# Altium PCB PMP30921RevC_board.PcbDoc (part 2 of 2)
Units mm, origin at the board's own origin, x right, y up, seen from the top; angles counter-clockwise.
Board outline 80.01 x 39.37 mm, 2 copper layers (Top Layer, Bottom Layer), stack 1.575 mm thick; 86 components, 35 nets, 198 pads, 30 vias.
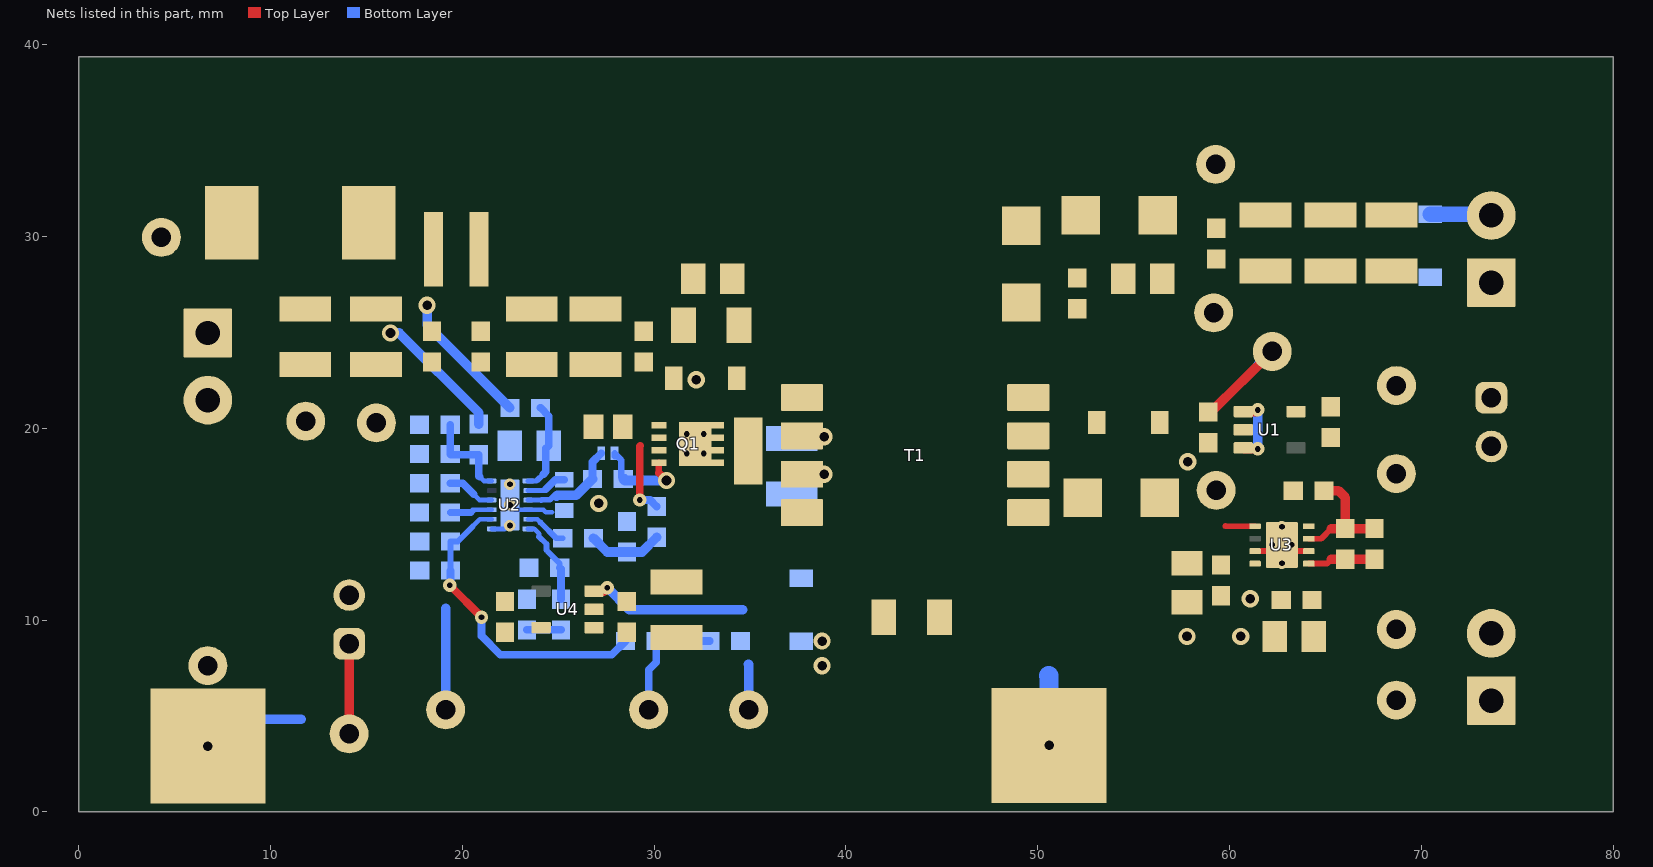
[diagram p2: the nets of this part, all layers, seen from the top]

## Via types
v1: diameter 0.6, hole 0.3, Top Layer to Bottom Layer, 11 vias
v2: diameter 0.9, hole 0.5, Top Layer to Bottom Layer, 8 vias
v3: diameter 0.7, hole 0.3, Top Layer to Bottom Layer, tented top, 3 vias
v4: diameter 0.9, hole 0.5, Top Layer to Bottom Layer, tented top, 2 vias
v5: diameter 0.9, hole 0.5, Top Layer to Bottom Layer, tented both sides, 2 vias
v6: diameter 0.7, hole 0.3, Top Layer to Bottom Layer, tented bottom, 2 vias
v7: diameter 0.7, hole 0.3, Top Layer to Bottom Layer, 1 vias
v8: diameter 0.9, hole 0.5, Top Layer to Bottom Layer, tented bottom, 1 vias

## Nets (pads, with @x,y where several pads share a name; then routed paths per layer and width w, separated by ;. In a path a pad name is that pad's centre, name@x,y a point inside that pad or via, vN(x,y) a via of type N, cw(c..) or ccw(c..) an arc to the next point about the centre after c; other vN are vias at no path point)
FB: C33.2 R15.1 R16.2 U3.3 | length 6.5
  Top Layer w0.31: U3.3@64.135,14.239 64.784,14.239 65.315,14.77
  Top Layer w0.5: R16.2@64.925,16.746 65.675,16.746 66.04,16.381 R15.1@66.04,14.77 ; 65.315,14.77 R15.1@66.04,14.77 ; C33.2@67.564,14.77 R15.1@66.04,14.77
GND: C2.2 C3.2 C4.2 C5.2 C6.2 C7.2 C8.2 C17.2 C22.2 C23.2 C24.2 C25.2 C26.2 C27.2 C28.2 C29.2 C30.2 C31.2 C32.2 Jmp1.2 Jmp5.2 pad.13@6.731,3.429 R8.1 R9.1 R10.1 R14.1 T1.4 TP3.1 TP15.1 TP16.1 TP17.1 U2.4 U2.7 U2.13@22.479,16.002 U4.2 | length 13.8
  Bottom Layer w0.25: U2.7@21.529,14.752 U2.13@22.213,14.752 ; v1(22.479,16.002) 22.729,15.752 U2.4@23.429,15.752 24.23,15.752 24.358,15.625 24.677,15.625
  Bottom Layer w0.5: pad.13@6.731,3.429 8.128,4.826 11.609,4.826 ; TP16.1@19.133,5.32 19.133,10.6
  other v1: 22.479,14.927 22.479,17.077
  other v2: 27.113,16.082
GNDsec: C10.2 C11.2 C12.2 C13.2 C15.2 C16.2 C18.2 C19.2 C20.2 C21.2 C24.1 D3.2 Jmp2.1 Jmp3.2 Jmp4.1 pad.13@50.596,3.463 R16.1 T1.5 TP4.1 TP8.1 TP11.1 U1.2 U3.2 U3.4 U3.7 U3.9 | length 6.7
  Top Layer w0.31: U3.7@61.335,13.589 62.41,13.589 U3.9@62.735,13.914 63.06,13.589 U3.2@64.135,13.589
  Bottom Layer w1: 50.577,7.098 50.596,7.079 pad.13@50.596,3.463
  other v1: 62.735,12.964 62.23,13.919 63.246,13.919 62.735,14.864
  other v2: 57.785,9.144 60.583,9.144 61.086,11.111 57.825,18.247
NetC1_1: C1.1 R1.1
NetC1_2: C1.2 D1.2 T1.8
NetC2_1: C2.1 C3.1 C4.1 D9.1 L1.1 R3.2 R4.2 | length 14.1
  Bottom Layer w0.5: v4(16.256,24.968) 16.705,24.968 20.857,20.816 R3.2@20.857,20.217 ; v2(18.161,26.416) 18.161,25.38 R4.2@22.479,21.062
NetC5_1: C5.1 C6.1 C7.1 C8.1 C9.1 L1.2 R2.2 T1.1
NetC9_2: C9.2 D4.1 R2.1
NetC10_1: C10.1 C11.1 C12.1 C13.1 D2.1 D3.1 Jmp2.2 R1.2 TP2.1 | length 3.2
  Bottom Layer w0.8: D3.1@70.475,31.16 73.588,31.16 Jmp2.2@73.65,31.097
NetC14_1: C14.1 D4.2 pad.14 Q1.5 Q1.6 Q1.7 Q1.8 Q1.9 T1.2
  other v1: 31.702,18.689 32.591,18.689 31.702,19.705 32.591,19.705
  other v4: 32.19,22.526
  other v5: 38.862,19.558
NetC14_2: C14.2 D6.2 T1.3
  other v5: 38.862,17.603
NetC15_1: C15.1 D5.1 TP5.1 U1.1 U1.3 | length 8.7
  Top Layer w0.5: C15.1@58.896,20.846 59.034,20.846 TP5.1@62.23,24.003 ; U1.3@60.718,18.971 60.766,18.923 v3(61.468,18.923) ; U1.1@60.718,20.871 61.384,20.871 v3(61.468,20.955)
  Bottom Layer w0.5: v3(61.468,18.923) v3(61.468,20.955) ; 61.468,23.28 TP5.1@61.843,23.656
NetC16_1: C16.1 Jmp3.1 TP6.1 U1.5
NetC17_1: C17.1 R4.1 U2.1 | length 4.7
  Bottom Layer w0.25: U2.1@23.429,17.252 23.878,17.252 23.909,17.283
  Bottom Layer w0.3: 23.909,17.283 24.23,17.605 24.23,17.607
  Bottom Layer w0.4: R4.1@24.079,21.062 24.511,20.63 C17.1@24.511,19.094 24.358,18.94 24.358,17.734 24.23,17.607
NetC18_1: C18.1 C19.1 D8.1 TP9.1 U3.5 U3.8 | length 1.6
  Top Layer w0.31: 59.784,14.897 59.792,14.889 U3.5@61.335,14.889
NetC20_1: C20.1 C21.1 C33.1 Jmp4.2 R15.2 TP10.1 U3.1 | length 3.5
  Top Layer w0.31: U3.1@64.135,12.939 65.084,12.939 65.315,13.17
  Top Layer w0.5: 65.315,13.17 R15.2@66.04,13.17 C33.1@67.564,13.17
NetC22_1: C22.1 U2.2 | length 2.1
  Bottom Layer w0.25: U2.2@23.429,16.752 24.279,16.752 24.346,16.819
  Bottom Layer w0.4: 24.346,16.819 24.84,17.314 C22.1@25.312,17.314
NetC23_1: C23.1 R6.2 R7.1 | length 3.9
  Bottom Layer w0.5: R6.2@26.835,14.268 27.557,13.545 C23.1@28.584,13.545 29.367,13.545 R7.1@30.138,14.316
NetC25_1: C25.1 R3.1 R9.2 U2.12 | length 4.9
  Bottom Layer w0.25: 20.903,17.466 21.117,17.252 U2.12@21.529,17.252
  Bottom Layer w0.4: C25.1@19.371,20.179 R9.2@19.371,18.655 19.409,18.617 R3.1@20.857,18.617 20.857,17.512 20.903,17.466
NetC26_1: C26.1 R11.2 U2.6 | length 4.6
  Bottom Layer w0.25: U2.6@23.429,14.752 23.742,14.752 24.003,14.491 24.003,14.346
  Bottom Layer w0.3: 24.003,14.346 24.385,13.964 24.385,13.648 24.485,13.548 24.485,13.543 25.079,12.949 C26.1@25.079,12.731
  Bottom Layer w0.4: C26.1@25.079,12.731 25.146,12.663 R11.2@25.146,11.087
NetC27_1: C27.1 Jmp5.1 TP12.1 U4.5 | length 4.7
  Top Layer w0.5: TP12.1@14.097,4.064 Jmp5.1@14.097,8.763
NetC28_1: C28.1 U2.9 | length 2.2
  Bottom Layer w0.25: 20.544,15.697 20.599,15.752 U2.9@21.529,15.752
  Bottom Layer w0.35: C28.1@19.371,15.607 20.453,15.607 20.544,15.697
NetC29_1: C29.1 R11.1 | length 1.8
  Bottom Layer w0.4: C29.1@23.368,9.487 R11.1@25.146,9.487
NetC30_1: C30.1 R12.2 R14.2 U2.8 | length 16.5
  Top Layer w0.4: v6(19.343,11.815) 20.998,10.159 v6(20.998,10.146)
  Bottom Layer w0.25: 20.544,14.882 20.914,15.252 U2.8@21.529,15.252
  Bottom Layer w0.3: C30.1@19.381,12.577 R14.2@19.381,14.101 19.763,14.101 20.544,14.882
  Bottom Layer w0.4: v6(19.343,11.815) 19.381,11.853 C30.1@19.381,12.577 ; v6(20.998,10.146) 20.998,9.171 21.977,8.192 27.793,8.192 R12.2@28.509,8.908
NetC31_1: C31.1 C32.1 D6.1 R13.2 TP14.1 U4.1 U4.3 | length 10.7
  Top Layer w0.5: U4.3@26.863,11.509 27.384,11.509 v3(27.559,11.684)
  Bottom Layer w0.5: v3(27.559,11.684) 28.701,10.542 34.622,10.542 ; 34.916,7.704 34.931,7.69 TP14.1@34.931,5.316
  other v2: 38.757,7.622
  other v8: 38.757,8.904
NetD1_1: D1.1 D2.2
NetD5_2: D5.2 T1.7
NetD7_1: D7.1 R5.1 U2.3 | length 5.3
  Bottom Layer w0.25: U2.3@23.429,16.252 24.119,16.252
  Bottom Layer w0.3: 24.119,16.252 24.137,16.27 24.574,16.27 24.768,16.464 24.909,16.464
  Bottom Layer w0.4: R5.1@26.788,17.352 26.788,18.239 D7.1@27.238,18.689
  Bottom Layer w0.5: 24.909,16.464 24.959,16.514 25.95,16.514 R5.1@26.788,17.352
NetD7_2: D7.2 Q1.4 R5.2 | length 5.2
  Top Layer w0.34: 30.251,17.67 Q1.4@30.251,18.205
  Top Layer w0.4: 30.251,17.67 v2(30.646,17.276)
  Bottom Layer w0.34: D7.2@27.938,18.539 D7.2@27.938,18.689 28.288,18.339 28.288,17.451 R5.2@28.388,17.352 R5.2@28.487,17.45
  Bottom Layer w0.5: R5.2@28.388,17.352 28.464,17.276 v2(30.646,17.276)
NetD8_2: D8.2 T1.6
NetD9_2: D9.2 Jmp1.1 TP1.1
NetQ1_1: Q1.1 Q1.2 Q1.3 R7.2 R8.2 | length 3.9
  Top Layer w0.4: v7(29.249,16.26) 29.249,19.053 29.277,19.081
  Bottom Layer w0.4: v7(29.249,16.26) 29.795,16.26 R7.2@30.138,15.916
NetR6_1: R6.1 U2.5 | length 2.2
  Bottom Layer w0.25: U2.5@23.429,15.252 23.913,15.252 24.079,15.086
  Bottom Layer w0.3: 24.079,15.086 24.898,14.268 R6.1@25.235,14.268
NetR10_2: R10.2 U2.10 | length 2.5
  Bottom Layer w0.25: 20.599,16.556 20.903,16.252 U2.10@21.529,16.252
  Bottom Layer w0.4: R10.2@19.371,17.131 20.024,17.131 20.599,16.556
NetR12_1: R12.1 R13.1 TP13.1 | length 6.5
  Bottom Layer w0.4: TP13.1@29.718,5.32 29.718,7.405 30.109,7.796 R12.1@30.109,8.908 32.901,8.908 R13.1@32.901,8.905
pads on no net: U1.4 U2.11 U2.13@22.479,15.317 U2.13@22.479,16.687 U3.6 U4.4

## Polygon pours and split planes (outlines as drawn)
NetC14_2 on Top Layer "TOP_LAYER_NETC14_2_P015" (solid, remove dead copper, pour order 15): 36.598,18.411 38.872,18.415 cw(c38.872,17.917) 39.37,17.917 39.37,17.274 cw(c38.969,17.274) 38.969,16.873 36.752,16.873 cw(c36.752,17.248) 36.377,17.248 36.377,18.189 cw(c36.598,18.189)
GND on Top Layer "TOP_LAYER_GND_P056" (solid, remove dead copper, pour order 56): 3.744,23.218 9.702,23.218 10.461,23.978 29.963,23.978 30.189,23.752 30.189,21.468 29.955,21.234 27.627,21.234 27.362,20.97 27.362,19.265 28.276,18.351 29.249,18.351 29.859,17.741 29.859,16.87 30.346,16.382 41.309,16.382 42.621,15.07 42.621,11.684 41.225,10.287 27.393,10.287 27.301,10.195 3.744,10.195
NetC27_1 on Top Layer "TOP_LAYER_NETC27_1_P055" (solid, remove dead copper, pour order 55): 24.688,9.908 12.913,9.908 12.827,9.821 12.827,7.319 13.161,6.985 22.485,6.985 24.688,9.188
NetC31_1 on Top Layer "TOP_LAYER_NETC31_1_P053" (solid, remove dead copper, pour order 53): 39.397,9.982 26.319,9.982 26.319,8.011 27.218,7.112 39.367,7.112
NetC14_1 on Top Layer "TOP_LAYER_NETC14_1_P052" (solid, remove dead copper, pour order 52): 32.27,16.946 cw(c32.27,17.955) 31.261,17.955 31.282,20.523 ccw(c30.312,20.523) 30.998,21.209 30.678,21.529 cw(c31.208,22.06) 30.458,22.06 30.458,23.068 cw(c30.849,23.068) 30.849,23.458 31.694,23.458 cw(c31.694,22.17) 32.982,22.17 ccw(c33.961,22.17) 33.961,21.192 34.909,21.192 cw(c34.909,19.893) 35.828,20.811 ccw(c36.903,21.887) 36.903,20.366 38.759,20.366 cw(c38.759,19.646) 39.479,19.646 39.479,19.627 cw(c38.606,19.627) 38.606,18.754 36.318,18.754 ccw(c36.318,18.351) 35.915,18.351 35.915,17.261 cw(c35.599,17.261) 35.599,16.946
NetQ1_1 on Top Layer "TOP_LAYER_NETQ1_1_P047" (solid, remove dead copper, pour order 47): 30.646,18.673 28.487,18.673 27.852,19.308 27.852,20.742 27.99,20.88 30.646,20.88
GNDsec on Top Layer "TOP_LAYER_GNDSEC_P045" (solid, remove dead copper, pour order 45): 44.196,13.335 45.085,14.224 48.472,14.224 51.833,10.863 51.833,9.242 44.196,9.242
GND on Top Layer "TOP_LAYER_GND_P044" (solid, remove dead copper, pour order 44): 42.596,9.193 41.343,9.193 39.37,11.166 39.026,11.166 37.875,12.317 37.875,14.193 42.018,14.193 42.621,13.589
NetC16_1 on Top Layer "TOP_LAYER_NETC16_1_P037" (solid, remove dead copper, pour order 37): 75.438,23.4 74.305,24.533 65.319,24.533 62.927,22.141 62.927,20.636 62.865,20.574 70.489,20.574 75.438,20.574
NetC15_1 on Top Layer "TOP_LAYER_NETC15_1_P036" (solid, remove dead copper, pour order 36): 55.88,19.706 57.121,19.706 57.697,20.282 59.382,20.282 59.621,20.521 61.155,20.521 61.292,20.659 61.292,21.195 61.086,21.401 58.412,21.401 58.07,21.059 55.88,21.059
GNDsec on Top Layer "TOP_LAYER_GNDSEC_P035" (solid, remove dead copper, pour order 35): 54.465,19.501 57.856,19.501 58.171,19.816 59.545,19.816 59.993,20.265 64.316,20.265 69.809,20.265 75.404,20.265 75.404,16.254 68.327,16.254 66.448,18.133 54.356,18.133
GNDsec on Top Layer "TOP_LAYER_GNDSEC_P034" (solid, remove dead copper, pour order 34): 54.907,10.194 58.517,10.194 58.838,10.515 58.811,10.542 58.811,11.811 55.516,11.811 55.118,12.209 55.118,18.344 55.516,18.742 55.516,23.58 54.744,23.58 53.751,22.587 53.751,11.342
NetC18_1 on Top Layer "TOP_LAYER_NETC18_1_P032" (solid, remove dead copper, pour order 32): 55.372,17.471 55.372,13.492 56.581,12.283 61.206,12.283 61.593,12.67 61.593,13.07 61.493,13.17 60.968,13.17 60.642,13.495 60.277,13.859 60.277,17.471
GNDsec on Top Layer "TOP_LAYER_GNDSEC_P031" (solid, remove dead copper, pour order 31): 63.859,15.662 64.473,15.047 64.473,14.692 63.819,14.692 63.575,14.448 63.575,12.499 63.291,12.215 63.291,7.552 63.73,7.112 75.404,7.112 75.438,7.146 75.438,4.318 56.359,4.318 47.738,12.939 47.738,15.957 48.097,16.316 50.78,16.291 50.78,15.096 51.431,14.445 53.59,14.445 56.224,11.811 61.397,11.811 61.95,12.364 61.95,16.596 62.575,17.221 63.859,17.221
NetC20_1 on Top Layer "TOP_LAYER_NETC20_1_P030" (solid, remove dead copper, pour order 30): 75.438,7.874 64.014,7.874 63.73,8.158 63.73,13.115 64.434,13.115 65.315,12.233 65.315,11.042 65.689,10.668 75.438,10.668
GNDsec on Top Layer "TOP_LAYER_GNDSEC_P029" (solid, remove dead copper, pour order 29): 75.438,25.33 61.809,25.33 57.949,21.47 52.65,21.47 52.65,23.582 53.602,24.533 53.602,25.654 53.965,26.017 57.794,26.017 58.584,26.807 58.584,29.259 75.008,29.259 75.438,28.829
NetD8_2 on Top Layer "TOP_LAYER_NETD8_2_P028" (solid, remove dead copper, pour order 28): 52.916,18.301 cw(c52.916,17.869) 53.348,17.869 53.348,15.38 cw(c53.051,15.38) 53.051,15.083 51.572,15.083 cw(c51.572,15.603) 51.052,15.603 51.052,16.284 ccw(c50.462,16.284) 50.462,16.873 48.222,16.873 cw(c48.222,17.35) 47.745,17.35 47.745,17.822 cw(c48.224,17.822) 48.224,18.301
NetD5_2 on Top Layer "TOP_LAYER_NETD5_2_P027" (solid, remove dead copper, pour order 27): 52.753,18.896 ccw(c52.753,19.706) 53.563,19.706 53.563,20.823 ccw(c53.348,20.823) 53.348,21.038 52.753,21.038 ccw(c52.753,19.937) 51.975,20.715 cw(c51.052,21.638) 51.052,20.333 48.19,20.333 ccw(c48.19,19.882) 47.738,19.882 47.738,19.255 ccw(c48.097,19.255) 48.097,18.896
NetC10_1 on Top Layer "TOP_LAYER_NETC10_1_P025" (solid, remove dead copper, pour order 25): 55.807,26.779 55.807,29.188 55.118,29.877 55.118,32.319 57.47,34.671 74.531,34.671 75.438,33.764 75.438,30.258 75.057,29.877 60.547,29.877 60.536,29.888 57.904,29.888 57.904,26.779
NetC1_1 on Top Layer "TOP_LAYER_NETC1_1_P024" (solid, remove dead copper, pour order 24): 51.335,27.308 52.678,27.308 53.09,26.897 55.118,26.897 55.118,28.69 51.442,28.69 51.335,28.583
NetD1_1 on Top Layer "TOP_LAYER_NETD1_1_P023" (solid, remove dead copper, pour order 23): 52.466,29.072 ccw(c52.466,30.208) 53.602,30.208 53.602,31.842 ccw(c52.597,31.842) 52.597,32.847 48.659,32.847 ccw(c48.659,32.008) 47.82,32.008 47.82,29.711 ccw(c48.459,29.711) 48.459,29.072
NetC1_2 on Top Layer "TOP_LAYER_NETC1_2_P022" (solid, remove dead copper, pour order 22): 51.201,20.871 48.402,20.871 cw(c48.402,21.619) 47.653,21.619 47.653,27.251 cw(c48.459,27.251) 48.459,28.057 49.876,28.057 cw(c49.876,27.308) 50.625,27.308 ccw(c51.154,27.308) 51.154,26.779 52.474,26.779 cw(c52.474,26.468) 52.785,26.468 52.785,25.33 cw(c50.31,25.33) 52.06,23.58 ccw(c52.98,22.66) 51.679,22.66 51.679,21.349 cw(c51.201,21.349)
NetC9_2 on Top Layer "TOP_LAYER_NETC9_2_P007" (solid, remove dead copper, pour order 7): 33.655,28.956 34.725,28.956 cw(c34.725,28.43) 35.251,28.43 35.251,22.26 cw(c34.774,22.26) 34.774,21.783 33.818,21.783 cw(c33.818,22.225) 33.376,22.225 33.376,28.677 cw(c33.655,28.677)
NetC5_1 on Top Layer "TOP_LAYER_NETC5_1_P006" (solid, remove dead copper, pour order 6): 20.345,24.482 20.345,33.02 35.687,33.02 38.608,30.099 38.608,20.834 36.489,20.834 36.264,21.059 36.264,28.482 35.413,29.333 33.192,29.333 32.67,28.811 32.67,24.982 32.17,24.482
NetC2_1 on Top Layer "TOP_LAYER_NETC2_1_P003" (solid, remove dead copper, pour order 3): 10.461,24.482 18.999,24.482 18.999,33.02 10.461,33.02
NetD9_2 on Top Layer "TOP_LAYER_NETD9_2_P002" (solid, remove dead copper, pour order 2): 9.398,23.6 9.398,33.02 3.81,33.02 3.81,23.638
GND on Bottom Layer "BOTTOM_LAYER_GND_P064" (solid, remove dead copper, pour order 64): 22.729,14.452 22.886,14.452 24.003,13.335 24.003,10.696 23.843,10.536 22.707,10.536 21.971,11.271 21.971,14.452
NetC14_1 on Bottom Layer "BOTTOM_LAYER_NETC14_1_P063" (solid, remove dead copper, pour order 63): 32.282,16.914 cw(c32.282,17.923) 31.273,17.923 31.295,20.491 ccw(c30.324,20.491) 31.011,21.178 30.69,21.498 cw(c31.221,22.028) 30.471,22.028 30.471,23.036 cw(c30.861,23.036) 30.861,23.427 31.707,23.427 cw(c31.707,22.139) 32.995,22.139 ccw(c33.973,22.139) 33.973,21.16 34.921,21.16 cw(c34.921,19.861) 35.84,20.78 ccw(c36.916,21.855) 36.916,20.334 38.772,20.334 cw(c38.772,19.614) 39.492,19.614 39.492,19.595 cw(c38.619,19.595) 38.619,18.722 36.331,18.722 ccw(c36.331,18.319) 35.928,18.319 35.928,17.23 cw(c35.612,17.23) 35.612,16.914
GND on Bottom Layer "BOTTOM_LAYER_GND_P062" (solid, remove dead copper, pour order 62): 3.731,2.455 14.175,2.455 14.941,3.221 14.941,20.877 15.994,21.93 21.61,21.93 22.404,21.137 22.404,19.534 22.845,19.094 23.776,20.025 26.868,20.025 28.151,21.308 29.6,21.308 29.6,23.389 30.189,23.978 32.19,23.978 32.695,24.482 32.695,28.835 33.192,29.333 35.413,29.333 36.264,28.482 36.264,21.059 36.489,20.834 38.608,20.834 38.608,30.099 35.687,33.02 3.81,33.02
GND on Bottom Layer "BOTTOM_LAYER_GND_P060" (solid, remove dead copper, pour order 60): 21.835,20.11 21.835,17.702 21.985,17.552 21.985,11.257 22.987,11.257 22.987,17.942 23.122,18.078 23.122,20.11
GND on Bottom Layer "BOTTOM_LAYER_GND_P058" (solid, remove dead copper, pour order 58): 21.717,14.859 21.083,14.859 20.382,14.158 20.382,11.951 19.999,11.569 18.5,11.569 18.5,20.755 18.351,20.904 17.244,20.904 16.891,20.551 16.891,19.685 15.706,18.5 15.706,10.904 17.062,9.548 20.868,9.548 21.75,10.43
GND on Bottom Layer "BOTTOM_LAYER_GND_P040" (solid, remove dead copper, pour order 40): 29.309,14.346 28.067,14.346 27.585,14.992 24.475,14.992 23.829,15.639 23.829,15.755 24.079,16.006 26.208,16.006 26.829,16.627 29.309,16.627
GNDsec on Bottom Layer "BOTTOM_LAYER_GNDSEC_P039" (solid, remove dead copper, pour order 39): 56.962,20.244 56.962,20.483 61.809,25.33 74.892,25.33 75.404,25.842 75.404,33.798 74.531,34.671 48.471,34.671 47.564,33.764 47.564,20.32
GNDsec on Bottom Layer "BOTTOM_LAYER_GNDSEC_P038" (solid, remove dead copper, pour order 38): 47.564,17.1 47.564,20.678 47.925,21.038 58.057,21.038 61.552,24.533 74.305,24.533 75.404,23.434 75.404,16.306 68.274,16.306 67.441,16.306 65.841,17.907 58.801,17.907 58.007,17.113
GNDsec on Bottom Layer "BOTTOM_LAYER_GNDSEC_P033" (solid, remove dead copper, pour order 33): 75.438,4.318 47.564,4.318 47.564,17.84 47.885,18.161 60.028,18.161 60.968,17.221 65.565,17.221 67.266,15.52 68.289,15.52 69.078,14.731 69.078,13.038 75.047,13.038 75.438,12.647
NetC31_1 on Bottom Layer "BOTTOM_LAYER_NETC31_1_P017" (solid, remove dead copper, pour order 17): 39.338,11.148 34.516,11.148 33.909,10.541 33.909,8.17 34.967,7.112 39.338,7.112
NetC14_2 on Bottom Layer "BOTTOM_LAYER_NETC14_2_P016" (solid, remove dead copper, pour order 16): 36.221,18.387 38.806,18.387 cw(c38.806,17.823) 39.37,17.823 39.37,12.465 cw(c38.528,12.465) 38.528,11.623 36.76,11.623 cw(c36.76,12.555) 35.828,12.555 35.828,18.017 cw(c36.221,18.017) 36.221,18.411

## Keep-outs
Keep-Out Layer:
  text ".Layer_Name" at 14.656,-21.806 h1.52

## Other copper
Top Layer:
  text ".Layer_Name" at 14.656,-21.806 h1.52
Bottom Layer:
  text ".Layer_Name" at 14.656,-21.806 h1.52

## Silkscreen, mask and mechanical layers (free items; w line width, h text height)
Top Overlay:
  text "'.PRJ_Number'.PCB_Rev" at 25.82,35.179 h2
  text "12Vs" at 79.055,29.472 h1 r90
  text "GND2" at 79.113,24.964 h1 r90
  text "VIN" at 1.897,24.119 h1 r90
  text "5Vs" at 77.15,20.672 h1 r90
  text "GND" at 1.897,19.284 h1 r90
  text "GND2" at 77.15,15.947 h1 r90
  text "GND" at 9.497,10.987 h1
  text "GND" at 5.414,9.48 h1
  text "5Vp" at 9.497,8.549 h1
  text "3.3Vs" at 79.113,8.182 h1 r90
  text "GND2" at 79.113,2.739 h1 r90
  text "priFB" at 33.76,2.588 h1
  text "AGND" at 18.241,2.455 h1
  text "NWA" at 29.401,2.421 h1
  text "LM51551 Flyback/SEPIC" at 54.571,0.749 h0.8
  text "10/2020" at 74.051,0.616 h0.8
  text ".Layer_Name" at 14.656,-21.806 h1.52
Bottom Overlay:
  text ".Layer_Name" at 14.656,-21.806 h1.52
Top Paste:
  text ".Layer_Name" at 14.656,-21.806 h1.52
Bottom Paste:
  text ".Layer_Name" at 14.656,-21.806 h1.52
Top Solder:
  text ".Layer_Name" at 14.656,-21.806 h1.52
  text ".Layer_Name" at 14.656,-21.806 h1.52
Bottom Solder:
  text "'.PRJ_Number' '.PCB_Rev'" at 22.871,30.129 h1.5
  text ".Layer_Name" at 14.656,-21.806 h1.52
Drill Guide:
  text ".Layer_Name" at 14.656,-21.806 h1.52
M1 Board Outline:
  the board outline again, w0.254
  text ".Layer_Name" at 14.656,-21.806 h1.52
M2 Board Dimensions:
  rectangle: 0,-6.985 3.175,-3.81
  rectangle: 3.175,-10.16 12.7,-6.985
  lines w0.178: 0,-6.985 25.4,-6.985 ; 3.175,-10.16 3.175,-3.81 ; 6.35,-10.16 6.35,-3.81 ; 12.7,-10.16 12.7,-3.81 ; 19.05,-10.16 19.05,-3.81 ; 0,-10.16 25.4,-10.16 25.4,-3.81 0,-3.81 0,-10.16
  text "'.Print_Date'  '.Print_Time'" at 4.098,40.144 h1.5
  text ".Layer_Name" at 14.656,-21.806 h1.52
M3 3D STEP Top:
  text ".Layer_Name" at 14.656,-21.806 h1.52
M4 3D STEP Bottom:
  text ".Layer_Name" at 14.656,-21.806 h1.52
M5 Assembly Top:
  lines w0.254: -7.417,-23.626 160.223,-23.626 ; -7.417,-18.462 160.274,-18.462 ; -7.417,-13.297 -7.417,-28.791 94.31,-28.791 160.274,-28.791 160.274,-13.297 -7.404,-13.297 -7.404,-28.791 32.614,-28.791 ; 55.194,-28.791 55.194,-13.297 ; 87.376,-18.462 87.376,-13.297 ; 108.712,-18.462 108.712,-13.297 ; 124.511,-28.956 124.511,-23.804
  text "COMPONENTS MARKED 'DNP' SHOULD NOT BE POPULATED." at 29.299,-8.09 h1.52
  text "ASSEMBLY VARIANT:" at 29.286,-11.024 h1.52
  text ".VariantName" at 55.601,-11.024 h1.52
  text "PCB VIEWED FROM TOP SIDE" at -5.804,-16.654 h1.52
  text "BOARD #:" at 57.099,-16.654 h1.52
  text ".PRJ_Number" at 70.955,-16.654 h1.52
  text "REV:" at 92.405,-16.654 h1.52
  text ".PCB_Rev" at 99.809,-16.654 h1.52
  text "SVN REV:" at 113.69,-16.654 h1.52
  text ".VersionControl_RevNumber" at 126.543,-16.654 h1.52
  text "TID #:" at 57.099,-21.819 h1.52
  text ".TID" at 70.955,-21.819 h1.52
  text "PLOT NAME =" at -5.804,-27.034 h1.52
  text ".plot_File_Name" at 14.656,-27.034 h1.52
  text "GENERATED    :" at 57.15,-27.034 h1.52
  text ".Print_Date" at 79.235,-27.034 h1.52
  text ".Print_Time" at 97.752,-27.034 h1.52
  text "TEXAS INSTRUMENTS" at 129.87,-27.034 h1.52
M6 Assembly Bottom:
  lines w0.254: -7.429,-18.474 160.261,-18.474 ; -7.379,-23.639 160.261,-23.639 ; 28.334,-28.969 28.334,-23.817 ; 44.133,-18.474 44.133,-13.31 ; 65.468,-18.474 65.468,-13.31 ; 97.65,-28.804 97.65,-13.31 ; 120.231,-28.804 160.249,-28.804 160.249,-13.31 -7.429,-13.31 -7.429,-28.804 58.534,-28.804 160.261,-28.804 160.261,-13.31
  text "COMPONENTS MARKED 'DNP' SHOULD NOT BE POPULATED." at 154.991,-8.077 h1.52
  text ".VariantName" at 128.473,-11.024 h1.52
  text "ASSEMBLY VARIANT:" at 154.864,-11.024 h1.52
  text ".VersionControl_RevNumber" at 26.302,-16.667 h1.52
  text "SVN REV:" at 39.154,-16.667 h1.52
  text ".PCB_Rev" at 53.035,-16.667 h1.52
  text "REV:" at 60.439,-16.667 h1.52
  text ".PRJ_Number" at 81.89,-16.667 h1.52
  text "BOARD #:" at 95.745,-16.667 h1.52
  text "PCB VIEWED FROM BOTTOM SIDE" at 158.648,-16.667 h1.52
  text ".TID" at 81.89,-21.831 h1.52
  text "TID #:" at 95.745,-21.831 h1.52
  text "TEXAS INSTRUMENTS" at 22.974,-27.047 h1.52
  text ".Print_Time" at 55.093,-27.047 h1.52
  text ".Print_Date" at 73.609,-27.047 h1.52
  text "GENERATED    :" at 95.694,-27.047 h1.52
  text ".plot_File_Name" at 138.189,-27.047 h1.52
  text "PLOT NAME =" at 158.648,-27.047 h1.52
M9 Title Sheet:
  drawing of 57 lines, arcs and shapes, not listed
  text "1" at 18.792,204.127 h1.78
  text "2" at 82.182,204.127 h1.78
  text "3" at 145.411,204.127 h1.78
  text "4" at 209.08,204.127 h1.78
  text "5" at 272.555,204.127 h1.78
  text "6" at 336.182,204.127 h1.78
  text "A" at -10.579,175.095 h1.78
  text "A" at 365.341,175.095 h1.78
  text "B" at -10.579,114.643 h1.78
  text "B" at 365.341,114.643 h1.78
  text "C" at -10.579,54.318 h1.78
  text "C" at 365.341,54.318 h1.78
  text "PROJECT TITLE:" at 288.125,7.048 h1.14
  text ".PRJ_Title" at 289.395,3.662 h1.78
  text "DESIGNED FOR:" at 288.125,-0.597 h1.14
  text ".PRJ_Customer" at 289.395,-4.153 h1.78
  text "D" at -10.579,-5.88 h1.78
  text "D" at 365.341,-5.88 h1.78
  text "FILE NAME:" at 288.125,-8.217 h1.14
  text ".PCB_File_Name_No_Path" at 289.395,-11.265 h1.78
  text "Texas Instruments (TI) and/or its licensors do not warrant the accuracy or completeness of this specification" at 161.9,-15.376 h1.14
  text "ENGINEER:" at 288.125,-15.583 h1.14
  text "LAYOUT BY:" at 326.352,-15.583 h1.14
  text "or any information contained therein. TI and/or its licensors do not warrant that this design will meet" at 160.757,-18.237 h1.14
  text ".PRJ_Engineer" at 289.395,-19.52 h1.78
  text ".PCB_Layout" at 327.635,-19.52 h1.78
  text "the specifications, will be suitable for your application or fit for any particular purpose, or will operate in" at 160.757,-21.099 h1.14
  text ".Layer_Name" at 14.656,-21.806 h1.52
  text "ALTIUM DESIGNER VERSION:" at 326.352,-23.457 h1.14
  text "an implementation. TI and/or its licensors do not warrant that the design is production worthy. You should" at 160.757,-23.961 h1.14
  text "completely validate and test your design implementation to confirm the system functionality for your application." at 161.9,-26.822 h1.14
  text ".print_Scale" at 289.395,-26.843 h1.78
  text ".Application_BuildNumber" at 327.635,-26.843 h1.78
  text "1" at 18.792,-32.093 h1.78
  text "2" at 82.182,-32.093 h1.78
  text "3" at 145.411,-32.093 h1.78
  text "4" at 209.08,-32.093 h1.78
  text "5" at 272.555,-32.093 h1.78
  text "6" at 336.182,-32.093 h1.78
M10 Fab Notes:
  drawing of 189 lines, arcs and shapes, not listed
  text "DESIGN INFORMATION" at 314.503,161.447 h1.52
  text "MIN. TRACK WIDTH:" at 298.131,158.091 h1.52
  text "8" at 325.976,158.091 h1.52
  text "MIL" at 329.907,158.091 h1.52
  text "MIN. CLEARANCE:" at 298.131,154.938 h1.52
  text "0.2" at 324.452,154.938 h1.52
  text "mm" at 329.907,154.938 h1.52
  text "MIN. VIA PAD SIZE:" at 298.131,151.785 h1.52
  text "24" at 325.214,151.785 h1.52
  text "MIL" at 329.907,151.785 h1.52
  text "0.05mm (2MIL)" at 315.784,148.486 h1.52
  text "MINIMUM ANNULAR RING" at 289.769,148.277 h1.52
  text "EXTERNAL" at 333.768,148.277 h1.52
  text "PER" at 294.849,145.48 h1.52
  text "IPC-D-275 CLASS 2 LEVEL C" at 300.437,145.48 h1.52
  text "MIL, HOLES" at 338.238,142.928 h1.52
  text "+/-" at 328.27,142.709 h1.52
  text "+/-" at 349.961,142.709 h1.52
  text "REGISTRATION TOLERANCES:" at 289.769,142.682 h1.52
  text "METAL" at 320.243,142.682 h1.52
  text "5" at 334.879,142.683 h1.52
  text "3" at 356.037,142.683 h1.52
  text "MIL" at 358.99,142.682 h1.52
  text "HOLE SIZE TOLERANCE (UNLESS OTHERWISE SPECIFIED):" at 289.769,140.185 h1.52
  text "+/-" at 349.961,140.112 h1.52
  text "3" at 356.037,140.085 h1.52
  text "MIL" at 358.99,140.085 h1.52
  text "MATERIAL:" at 287.87,136.589 h1.52
  text "FR-4 High Tg" at 312.926,133.324 h1.52
  text "X" at 309.257,133.122 h1.52
  text "FR-408" at 298.563,133.007 h1.52
  text "OTHER" at 336.358,133.007 h1.52
  text "62 MIL (1.6mm) +/-10%" at 306.694,129.374 h1.52
  text "X" at 303.643,129.312 h1.52
  text "THICKNESS:" at 289.769,129.165 h1.52
  text "OTHER" at 339.33,129.165 h1.52
  text "TOLERANCE:" at 289.769,125.652 h1.52
  text "X" at 311.314,125.652 h1.52
  text "ANSI IPC-6012 TYPE 3 CLASS 2" at 315.836,125.652 h1.52
  text "OTHER +/-" at 315.835,121.989 h1.52
  text "BOW & TWIST:" at 289.769,118.302 h1.52
  text "X" at 311.314,118.302 h1.52
  text "ANSI IPC-6012 TYPE 3 CLASS 2" at 315.836,118.302 h1.52
  text "OTHER +/-" at 315.835,114.576 h1.52
  text "DRILLING:" at 287.87,111.258 h1.52
  text "NC_DRILL FILES" at 332.599,108.586 h1.52
  text "REFERENCE:" at 289.769,108.486 h1.52
  text "X" at 306.463,108.484 h1.52
  text "AS SHOWN" at 310.984,108.486 h1.52
  text "X" at 329.348,108.486 h1.52
  text "OTHER" at 340.168,104.873 h1.52
  text "PTH COPPER THICKNESS:" at 289.761,104.783 h1.52
  text "X" at 318.697,104.783 h1.52
  text "20-30 um" at 321.948,104.783 h1.52
  text "BOARD FINISH:" at 287.87,101.034 h1.52
  text "SILKSCREEN:" at 291.812,98.237 h1.52
  text "X" at 316.14,98.237 h1.52
  text "TOP" at 319.112,98.237 h1.52
  text "X" at 329.094,98.237 h1.52
  text "BOTTOM" at 332.091,98.237 h1.52
  text "SILKSCREEN COLOR:" at 291.812,94.295 h1.52
  text "X" at 316.115,94.295 h1.52
  text "WHITE" at 319.112,94.295 h1.52
  text "OTHER" at 332.091,94.295 h1.52
  text "X" at 319.442,90.652 h1.52
  text "GREEN" at 322.439,90.652 h1.52
  text "OTHER" at 338.136,90.652 h1.52
  text "SOLDER RESIST COLOR:" at 291.812,90.477 h1.52
  text "X" at 319.442,86.734 h1.52
  text "MATTE" at 322.439,86.734 h1.52
  text "SEMI-GLOSS" at 338.125,86.717 h1.52
  text "IMMERSION GOLD (ENIG)" at 314.819,82.345 h1.52
  text "ENEPIG" at 348.793,82.162 h1.52
  text "SURFACE FINISH:" at 287.87,82.136 h1.52
  text "X" at 310.298,82.136 h1.52
  text "IMM. TIN/SILVER OR EQUIV" at 296.24,78.649 h1.52
  text "OTHER" at 332.599,78.549 h1.52
  text "ARRAY/PANEL:" at 287.87,74.602 h1.52
  text "CUT AND TRIM PER M1 BOARD OUTLINE" at 314.819,74.393 h1.52
  text "N.C. ROUTE" at 314.819,70.94 h1.52
  text "X" at 332.295,70.94 h1.52
  text "V. SCORE" at 336.816,70.94 h1.52
  text "CERTIFICATION:" at 287.87,67.66 h1.52
  text "MATERIALS AND WORKMANSHIP FOR ALL PCBS" at 306.285,67.66 h1.52
  text "TO MEET OR EXCEED THE REQUIREMENTS OF:" at 306.285,65.271 h1.52
  text "X" at 297.078,62.003 h1.52
  text "ANSI IPC-A-600F CLASS ->" at 300.329,62.003 h1.52
  text "X" at 342.188,62.003 h1.52
  text "2" at 344.982,62.003 h1.52
  text "1" at 336.981,61.965 h1.52
  text "3" at 353.973,61.965 h1.52
  text "X" at 317.702,58.252 h1.52
  text "RoHS" at 320.953,58.252 h1.52
  text "OTHER" at 337.321,58.252 h1.52
  text "PER ORDER" at 347.407,58.252 h1.52
  text "ALL BOARDS MUST MEET OR EXCEED UL94-V0 REQUIREMENTS." at 288.569,54.345 h1.52
  text "PCB MUST BEAR THE UL94V-0 UL REGISTERED MATERIAL ID NUMBER" at 288.569,51.397 h1.52
  text "ADDITIONAL REQUIREMENTS:" at 287.87,47.094 h1.52
  text "MICROSECTION:" at 289.769,44.373 h1.52
  text "YES" at 312.775,44.373 h1.52
  text "REQUIRED" at 334.657,40.707 h1.52
  text "BARE BOARD ELEC. TEST:" at 289.769,40.634 h1.52
  text "NONE" at 322.935,40.634 h1.52
  text "X" at 331.66,40.634 h1.52
  text "PER ORDER" at 349.693,40.634 h1.52
  text "XX MIL VIAS REQUIRE NON-CONDUCTIVE FILL AND PLANARIZE" at 294.04,35.428 h1.5
  text "XX MIL VIAS REQUIRE CONDUCTIVE FILL AND PLANARIZE" at 294.243,32.787 h1.52
  text "OUTER XX MIL TRACES REQUIRE 50 OHM SINGLE-ENDED IMPEDANCE" at 294.218,28.637 h1.47
  text "LAYER 2 & 3 (INNER LAYERS) XX MIL WIDE, XX MIL SPACE / TRACES REQUIRE 100 OHM DIFFERENTIAL IMPEDANCE" at 294.015,22.65 h1.52
  text ".Layer_Name" at 14.656,-21.806 h1.52
M11 Gerber Information:
  lines w0.254: -7.417,-23.626 160.223,-23.626 ; -7.417,-18.462 160.274,-18.462 ; -7.417,-13.297 -7.417,-28.791 94.31,-28.791 160.274,-28.791 160.274,-13.297 -7.404,-13.297 -7.404,-28.791 32.614,-28.791 ; 55.194,-28.791 55.194,-13.297 ; 87.376,-18.462 87.376,-13.297 ; 108.712,-18.462 108.712,-13.297 ; 124.511,-28.956 124.511,-23.804
  text "ALL ARTWORK VIEWED FROM TOP SIDE" at -5.804,-16.654 h1.52
  text "BOARD #:" at 57.099,-16.654 h1.52
  text ".PRJ_Number" at 70.955,-16.654 h1.52
  text "REV:" at 92.405,-16.654 h1.52
  text ".PCB_Rev" at 99.809,-16.654 h1.52
  text "SVN REV:" at 113.69,-16.654 h1.52
  text ".VersionControl_RevNumber" at 126.543,-16.654 h1.52
  text "LAYER NAME =" at -5.804,-21.806 h1.52
  text "TID #:" at 57.099,-21.819 h1.52
  text ".TID" at 70.955,-21.819 h1.52
  text "PLOT NAME =" at -5.804,-27.034 h1.52
  text ".plot_File_Name" at 14.656,-27.034 h1.52
  text "GENERATED    :" at 57.15,-27.034 h1.52
  text ".Print_Date" at 79.235,-27.034 h1.52
  text ".Print_Time" at 97.752,-27.034 h1.52
  text "TEXAS INSTRUMENTS" at 129.87,-27.034 h1.52
M12 Stackup:
  drawing of 191 lines, arcs and shapes, not listed
  text "Layer" at 249.119,194.31 h1.52
  text "Name" at 259.531,194.31 h1.52
  text "Material" at 283.147,194.31 h1.52
  text "Thickness" at 304.985,194.31 h1.52
  text "Constant" at 321.49,194.31 h1.52
  text "Board Layer Stack" at 335.965,194.31 h1.52
  text "Top Overlay" at 259.531,191.262 h1.52
  text "Top Solder" at 259.531,188.214 h1.52
  text "Solder Resist" at 283.147,188.214 h1.52
  text "0.40mil" at 304.985,188.214 h1.52
  text "3.5" at 321.49,188.214 h1.52
  text "1" at 249.119,185.166 h1.52
  text "Top Layer" at 259.531,185.166 h1.52
  text "1.40mil" at 304.985,185.166 h1.52
  text "Dielectric1" at 259.531,182.118 h1.52
  text "FR-4" at 283.147,182.118 h1.52
  text "59.20mil" at 304.985,182.118 h1.52
  text "4.8" at 321.49,182.118 h1.52
  text "2" at 249.119,179.07 h1.52
  text "Bottom Layer" at 259.531,179.07 h1.52
  text "1.40mil" at 304.985,179.07 h1.52
  text "Bottom Solder" at 259.531,176.022 h1.52
  text "Solder Resist" at 283.147,176.022 h1.52
  text "0.40mil" at 304.985,176.022 h1.52
  text "3.5" at 321.49,176.022 h1.52
  text "Bottom Overlay" at 259.531,172.974 h1.52
  text ".Layer_Name" at 14.656,-21.806 h1.52
M13 Component Bodies Top:
  text ".Layer_Name" at 14.656,-21.806 h1.52
M14 Component Bodies Bottom:
  text ".Layer_Name" at 14.656,-21.806 h1.52
M15 Courtyards Top:
  text ".Layer_Name" at 14.656,-21.806 h1.52
M16 Courtyards Bottom:
  text ".Layer_Name" at 14.656,-21.806 h1.52
Drill Drawing:
  circle w0.254: c136.241,74.689 r0.703
  lines w0.254: 135.538,77.149 136.944,77.149 136.944,78.554 135.538,78.554 135.538,77.149 ; 135.538,80.662 135.89,80.662 136.241,80.311 136.593,80.662 136.944,80.662 136.593,81.014 136.944,81.365 136.593,81.365 136.241,81.716 135.89,81.365 135.538,81.365 135.89,81.014 135.538,80.662 ; 135.538,83.473 136.241,83.825 136.944,83.473 136.593,84.176 136.944,84.879 136.241,84.527 135.538,84.879 135.89,84.176 135.538,83.473
  lines w0.305: 134.264,73.038 216.362,73.038 ; 134.264,85.687 216.362,85.687 ; 142.85,69.875 142.85,88.849 ; 151.287,69.875 151.287,88.849 ; 167.453,69.875 167.453,88.849 ; 174.037,69.875 174.037,88.849 ; 183.568,69.875 183.568,88.849 ; 201.972,69.875 201.972,88.849 ; 134.264,69.875 216.362,69.875 216.362,88.849 134.264,88.849 134.264,69.875
  text "Symbol" at 136.162,86.636 h1.83
  text "Quantity" at 143.799,86.636 h1.83
  text "Finished Hole Size" at 152.235,86.636 h1.83
  text "Plated" at 168.402,86.636 h1.83
  text "Hole Type" at 174.986,86.636 h1.83
  text "Drill Layer Pair" at 184.517,86.636 h1.83
  text "Hole Tolerance" at 202.92,86.636 h1.83
  text "17" at 143.799,83.473 h1.52
  text "11.81mil (0.300mm)" at 152.235,83.473 h1.52
  text "PTH" at 168.402,83.473 h1.52
  text "Round" at 174.986,83.473 h1.52
  text "Top Layer - Bottom Layer" at 184.517,83.473 h1.52
  text "15" at 143.799,80.311 h1.52
  text "19.69mil (0.500mm)" at 152.235,80.311 h1.52
  text "PTH" at 168.402,80.311 h1.52
  text "Round" at 174.986,80.311 h1.52
  text "Top Layer - Bottom Layer" at 184.517,80.311 h1.52
  text "20" at 143.799,77.149 h1.52
  text "40.00mil (1.016mm)" at 152.235,77.149 h1.52
  text "PTH" at 168.402,77.149 h1.52
  text "Round" at 174.986,77.149 h1.52
  text "Top Layer - Bottom Layer" at 184.517,77.149 h1.52
  text "6" at 143.799,73.986 h1.52
  text "50.00mil (1.270mm)" at 152.235,73.986 h1.52
  text "PTH" at 168.402,73.986 h1.52
  text "Round" at 174.986,73.986 h1.52
  text "Top Layer - Bottom Layer" at 184.517,73.986 h1.52
  text "58 Total" at 143.799,70.824 h1.52
  text ".Layer_Name" at 14.656,-21.806 h1.52
M17 Embedded Cavity:
  text ".Layer_Name" at 14.656,-21.806 h1.52
M18 Embedded Assembly:
  text ".Layer_Name" at 14.656,-21.806 h1.52
M19 Embedded Keepout:
  text ".Layer_Name" at 14.656,-21.806 h1.52

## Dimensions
0,-10.16 to 25.4,-10.16 on M2 Board Dimensions
0,0 to 0,39.37 on M2 Board Dimensions
0,0 to 80.01,0 on M2 Board Dimensions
